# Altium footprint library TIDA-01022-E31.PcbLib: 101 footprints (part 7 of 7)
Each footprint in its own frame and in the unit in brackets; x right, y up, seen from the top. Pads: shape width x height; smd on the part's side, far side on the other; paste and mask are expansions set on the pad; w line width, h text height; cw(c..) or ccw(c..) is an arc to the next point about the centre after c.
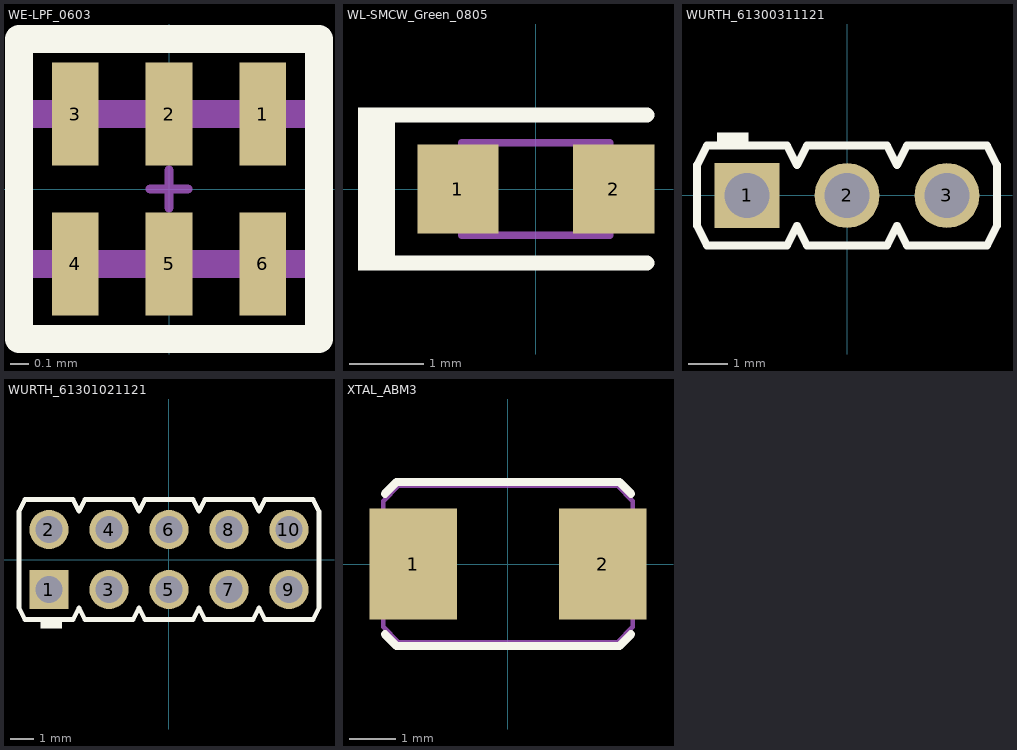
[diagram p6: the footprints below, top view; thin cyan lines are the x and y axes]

## WE-LPF_0603 [mm] "WE-LPF Multilayer Chip Low-Pass Filter, 0603"
height 0.6
pads (6):
  rect 0.25x0.55 smd mask+0: 1(0.5,0.4) 2(0,0.4) 3(-0.5,0.4) 4(-0.5,-0.4) 5(0,-0.4) 6(0.5,-0.4)
Top Overlay:
  lines w0.15: -0.8,-0.8 -0.8,0.8 0.8,0.8 0.8,-0.8 -0.8,-0.8
Mechanical 13:
  lines w0.15: -0.8,-0.4 0.8,-0.4 0.8,0.4 -0.8,0.4 -0.8,-0.4
Mechanical 15:
  lines w0.05: -0.1,0 0.1,0 ; 0,-0.1 0,0.1
3D body "STEP-WE-LPF-0603-rev1.stp": height 0.62, standoff 0.02, extent -0.8,-0.4 0.8,0.4

## WL-SMCW_Green_0805 [mm] "SMD, 2-Leads, Body 2x1.25mm"
height 0.8
pads (2):
  rect 1.1x1.2 smd: 1(-1.05,0) 2(1.05,0)
Top Overlay:
  rectangle: -2.4,-1.099 -2,1.101
  lines w0.2: 1.5,-1 -2,-1 -2,1 1.5,1
Mechanical 5:
  lines w0.1: -1,-0.625 1,-0.625 1,-0.2 cw(c1,0) 1,0.2 1,0.625 -1,0.625 -1,0.425 -1,0.35 -1,0.2 cw(c-1,0) -1,-0.2 -1,-0.35 -1,-0.425 -1,-0.625
  text ".Designator" at -0.726,0.837 h0.51
3D body "WL-SMCW_0805.stp": height 0.7, standoff 0, extent -1,-0.625 1,0.625

## WURTH_61300311121 [mm] "Header, 2.54mm, 3x1, TH"
height 8.89
pads (3):
  rect 1.65x1.65 hole 1.15: 1(-2.54,0)
  round 1.65 hole 1.15: 2(0,0) 3(2.54,0)
Top Overlay:
  rectangle: -3.3,1.3 -2.5,1.6
  lines w0.2: -3.81,-0.77 -3.81,0.77 -3.56,1.27 -1.52,1.27 -1.27,0.77 -1.02,1.27 1.02,1.27 1.27,0.77 1.52,1.27 3.56,1.27 3.81,0.77 3.81,-0.77 3.56,-1.27 1.52,-1.27 1.27,-0.77 1.02,-1.27 -1.02,-1.27 -1.27,-0.77 -1.52,-1.27 -3.56,-1.27 -3.81,-0.77
Mechanical 5:
  lines w0.1: -3.81,-0.77 -3.56,-1.27 -1.52,-1.27 -1.27,-0.77 -1.02,-1.27 1.02,-1.27 1.27,-0.77 1.52,-1.27 3.56,-1.27 3.81,-0.77 3.81,0.77 3.56,1.27 1.52,1.27 1.27,0.77 1.02,1.27 -1.02,1.27 -1.27,0.77 -1.52,1.27 -3.56,1.27 -3.81,0.77 -3.81,-0.77
  text ".Designator" at 1.397,0.356 h0.51
3D body "61300311121.stp": height 8.54, standoff -3, extent -3.81,-1.27 3.81,1.27

## WURTH_61301021121 [mm] "Header, 2.54mm, 5x2, TH"
height 8.89
pads (10):
  rect 1.65x1.65 hole 1.15: 1(-5.08,-1.27)
  round 1.65 hole 1.15: 2(-5.08,1.27) 3(-2.54,-1.27) 4(-2.54,1.27) 5(0,-1.27) 6(0,1.27) 7(2.54,-1.27) 8(2.54,1.27) 9(5.08,-1.27) 10(5.08,1.27)
Top Overlay:
  rectangle: -5.436,-2.916 -4.536,-2.616
  lines w0.2: -6.35,-2.04 -6.1,-2.54 -4.06,-2.54 -3.81,-2.04 -3.56,-2.54 -1.52,-2.54 -1.27,-2.04 -1.02,-2.54 1.02,-2.54 1.27,-2.04 1.52,-2.54 3.56,-2.54 3.81,-2.04 4.06,-2.54 6.1,-2.54 6.35,-2.04 6.35,2.04 6.1,2.54 4.06,2.54 3.81,2.04 3.56,2.54 1.52,2.54 1.27,2.04 1.02,2.54 -1.02,2.54 -1.27,2.04 -1.52,2.54 -3.56,2.54 -3.81,2.04 -4.06,2.54 -6.1,2.54 -6.35,2.04 -6.35,-2.04
Mechanical 5:
  lines w0.1: -6.35,-2.04 -6.35,2.04 -6.1,2.54 -4.06,2.54 -3.81,2.04 -3.56,2.54 -1.52,2.54 -1.27,2.04 -1.02,2.54 1.02,2.54 1.27,2.04 1.52,2.54 3.56,2.54 3.81,2.04 4.06,2.54 6.1,2.54 6.35,2.04 6.35,-2.04 6.1,-2.54 4.06,-2.54 3.81,-2.04 3.56,-2.54 1.52,-2.54 1.27,-2.04 1.02,-2.54 -1.02,-2.54 -1.27,-2.04 -1.52,-2.54 -3.56,-2.54 -3.81,-2.04 -4.06,-2.54 -6.1,-2.54 -6.35,-2.04
  text ".Designator" at 1.549,-0.711 h0.51
3D body "61301021121.stp": height 8.54, standoff -3, extent -6.35,-2.54 6.35,2.54

## XTAL_ABM3 [mm] "Abracon recommended land pattern 12.28.10"
height 1.3
pads (2):
  rect 1.9x2.4 smd: 1(-2.05,0) 2(2.05,0)
Top Overlay:
  lines w0.178: -2.667,-1.524 -2.413,-1.778 0,-1.778 2.413,-1.778 2.667,-1.524 ; -2.667,1.524 -2.413,1.778 0,1.778 2.413,1.778 2.667,1.524
Mechanical 5:
  lines w0.1: -2.7,-1.364 -2.364,-1.7 2.364,-1.7 2.7,-1.364 2.7,1.364 2.364,1.7 -2.364,1.7 -2.7,1.364 -2.7,-1.364
  text ".Designator" at -0.242,0.342 h0.51
3D body "Abracon_ABM3.stp": height 1.3, standoff 0, extent -2.597,-1.698 2.603,1.702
